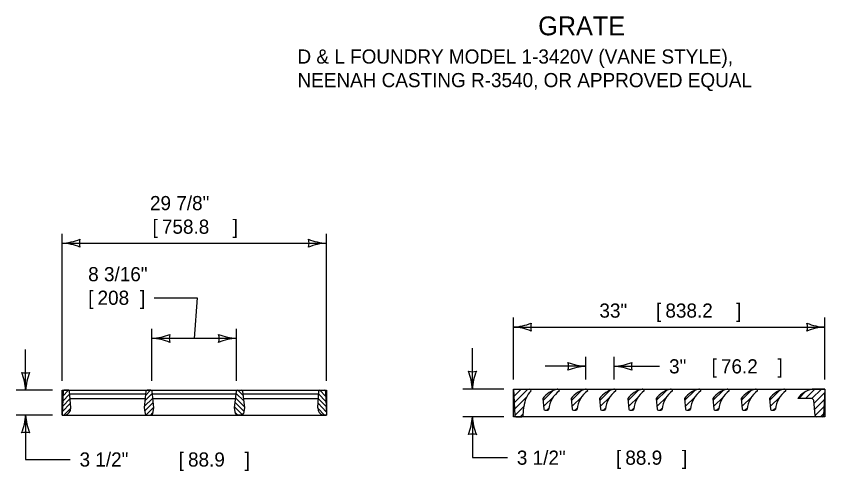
# Model space of a CAD drawing. Extents: x 49991.4 to 50041.6, y 49987.6 to 50011.4.
# Drawn here: x 50032.971 to 50036.399, y 49993.608 to 49995.536 of the extents above; entities that cross this region are included whole.
import ezdxf

# ---------------------------------------------------------------- set-up
doc = ezdxf.new("R2010")
doc.units = 0
for name, color, linetype in [('Default', 7, 'Continuous'), ('Level 1', 7, 'Continuous'), ('Level 2', 7, 'Continuous'), ('Level 3', 7, 'Continuous')]:
    doc.layers.add(name, color=color, linetype=linetype)

# ---------------------------------------------------------------- blocks, each defined once
blk = doc.blocks.new('POINT_DISPLAY')
at = {"layer": 'Default'}
blk.add_line((0, 0), (0, 0), dxfattribs=at)

msp = doc.modelspace()

# ---------------------------------------------------------------- linework, layer by layer
at = {"layer": 'Level 1'}
for p, q in [((50033.1659, 49993.934), (50033.1695, 49993.934)), ((50033.17, 49993.9459), (50033.1674, 49993.8783)), ((50033.1683, 49993.9023), (50033.1988, 49993.934)), ((50033.1692, 49993.9244), (50033.1934, 49993.9496)), ((50033.1943, 49993.9496), (50033.1737, 49993.9496)), ((50033.2026, 49993.8746), (50033.198, 49993.946)), ((50033.1988, 49993.934), (50033.5196, 49993.934)), ((50033.5209, 49993.9463), (50033.5134, 49993.8746)), ((50033.5165, 49993.9043), (50033.5483, 49993.9361)), ((50033.519, 49993.928), (50033.5406, 49993.9496)), ((50033.5418, 49993.9496), (50033.5263, 49993.9496)), ((50033.5547, 49993.8746), (50033.5472, 49993.9463)), ((50033.5485, 49993.934), (50033.9036, 49993.934)), ((50033.8974, 49993.8746), (50033.9049, 49993.9463)), ((50033.9356, 49993.9043), (50033.9038, 49993.9361)), ((50033.9103, 49993.9496), (50033.9258, 49993.9496)), ((50033.9331, 49993.928), (50033.9115, 49993.9496)), ((50033.9312, 49993.9463), (50033.9386, 49993.8746)), ((50033.9325, 49993.934), (50034.2533, 49993.934)), ((50034.2495, 49993.8746), (50034.254, 49993.946)), ((50034.2837, 49993.9023), (50034.2533, 49993.934)), ((50034.2578, 49993.9496), (50034.2783, 49993.9496)), ((50034.2829, 49993.9244), (50034.2587, 49993.9496)), ((50034.2821, 49993.9459), (50034.2846, 49993.8783)), ((50034.2825, 49993.934), (50034.2862, 49993.934)), ((50035.0786, 49993.9549), (50035.0845, 49993.8421)), ((50035.0786, 49993.9549), (50035.1461, 49993.9549)), ((50035.0786, 49993.8374), (50035.0786, 49993.9549)), ((50035.0788, 49993.9499), (50035.0839, 49993.9549)), ((50035.0802, 49993.923), (50035.1122, 49993.9549)), ((50035.0816, 49993.8961), (50035.1404, 49993.9549)), ((50035.2045, 49993.9058), (50035.2477, 49993.949)), ((50035.3245, 49993.9059), (50035.367, 49993.9484)), ((50035.4445, 49993.9059), (50035.487, 49993.9484)), ((50035.5645, 49993.9059), (50035.6071, 49993.9484)), ((50035.6845, 49993.9059), (50035.7271, 49993.9484)), ((50035.8045, 49993.9059), (50035.8471, 49993.9484)), ((50035.9245, 49993.9059), (50035.9671, 49993.9484)), ((50036.0445, 49993.9059), (50036.0871, 49993.9484)), ((50036.1645, 49993.9059), (50036.2071, 49993.9484)), ((50036.2885, 49993.9149), (50036.3173, 49993.9438)), ((50036.3168, 49993.9149), (50036.3568, 49993.9549)), ((50036.3442, 49993.9141), (50036.385, 49993.9549)), ((50036.3986, 49993.9549), (50036.3443, 49993.9549)), ((50036.3525, 49993.8941), (50036.3978, 49993.9394)), ((50036.3986, 49993.9549), (50036.3927, 49993.8421)), ((50033.1659, 49993.9141), (50033.1688, 49993.9141)), ((50033.1675, 49993.8802), (50033.2001, 49993.9141)), ((50033.2001, 49993.9141), (50033.5176, 49993.9141)), ((50033.5141, 49993.8806), (50033.5503, 49993.9168)), ((50033.5158, 49993.8612), (50033.5523, 49993.8976)), ((50033.5506, 49993.9141), (50033.9015, 49993.9141)), ((50033.9363, 49993.8612), (50033.8998, 49993.8976)), ((50033.938, 49993.8806), (50033.9018, 49993.9168)), ((50033.9345, 49993.9141), (50034.252, 49993.9141)), ((50034.2846, 49993.8802), (50034.252, 49993.9141)), ((50034.2833, 49993.9141), (50034.2862, 49993.9141)), ((50035.083, 49993.8692), (50035.1351, 49993.9213)), ((50035.2036, 49993.9149), (50035.2081, 49993.8694)), ((50035.207, 49993.8801), (50035.2489, 49993.9219)), ((50035.3236, 49993.9149), (50035.3281, 49993.8694)), ((50035.327, 49993.8802), (50035.37, 49993.9232)), ((50035.4436, 49993.9149), (50035.4481, 49993.8694)), ((50035.4471, 49993.8802), (50035.49, 49993.9231)), ((50035.5636, 49993.9149), (50035.5681, 49993.8694)), ((50035.5671, 49993.8802), (50035.61, 49993.9231)), ((50035.6836, 49993.9149), (50035.6882, 49993.8694)), ((50035.6871, 49993.8802), (50035.73, 49993.9231)), ((50035.8036, 49993.9149), (50035.8082, 49993.8694)), ((50035.8071, 49993.8802), (50035.8489, 49993.922)), ((50035.9236, 49993.9149), (50035.9282, 49993.8694)), ((50035.9271, 49993.8802), (50035.9689, 49993.922)), ((50036.0436, 49993.9149), (50036.0482, 49993.8694)), ((50036.0471, 49993.8802), (50036.0889, 49993.922)), ((50036.1636, 49993.9149), (50036.1682, 49993.8694)), ((50036.1671, 49993.8802), (50036.2089, 49993.922)), ((50036.342, 49993.9149), (50036.2836, 49993.9149)), ((50036.3571, 49993.842), (50036.3515, 49993.9058)), ((50036.3548, 49993.8681), (50036.3963, 49993.9095)), ((50033.1674, 49993.8783), (50033.1657, 49993.8446)), ((50033.1664, 49993.8578), (50033.2013, 49993.8943)), ((50033.1741, 49993.8446), (50033.2026, 49993.8744)), ((50033.5134, 49993.8746), (50033.5176, 49993.8508)), ((50033.5217, 49993.8458), (50033.5543, 49993.8784)), ((50033.5505, 49993.8508), (50033.5547, 49993.8746)), ((50033.9016, 49993.8508), (50033.8974, 49993.8746)), ((50033.9304, 49993.8458), (50033.8978, 49993.8784)), ((50033.9386, 49993.8746), (50033.9345, 49993.8508)), ((50034.278, 49993.8446), (50034.2495, 49993.8744)), ((50034.2857, 49993.8578), (50034.2507, 49993.8943)), ((50034.2846, 49993.8783), (50034.2863, 49993.8446)), ((50035.0845, 49993.8424), (50035.1235, 49993.8814)), ((50035.1199, 49993.842), (50035.1233, 49993.88)), ((50035.2131, 49993.8649), (50035.224, 49993.8649)), ((50035.2202, 49993.8649), (50035.2299, 49993.8746)), ((50035.3331, 49993.8649), (50035.344, 49993.8649)), ((50035.3401, 49993.8649), (50035.3501, 49993.8749)), ((50035.4531, 49993.8649), (50035.464, 49993.8649)), ((50035.4601, 49993.8649), (50035.4701, 49993.8749)), ((50035.5731, 49993.8649), (50035.584, 49993.8649)), ((50035.5801, 49993.8649), (50035.5901, 49993.8749)), ((50035.6931, 49993.8649), (50035.704, 49993.8649)), ((50035.7001, 49993.8649), (50035.7101, 49993.8749)), ((50035.8131, 49993.8649), (50035.824, 49993.8649)), ((50035.8201, 49993.8649), (50035.8304, 49993.8752)), ((50035.9331, 49993.8649), (50035.944, 49993.8649)), ((50035.9401, 49993.8649), (50035.9504, 49993.8752)), ((50036.0532, 49993.8649), (50036.0641, 49993.8649)), ((50036.0601, 49993.8649), (50036.0704, 49993.8752)), ((50036.1732, 49993.8649), (50036.1841, 49993.8649)), ((50036.1801, 49993.8649), (50036.1904, 49993.8752)), ((50036.3571, 49993.8421), (50036.3947, 49993.8797)), ((50033.1657, 49993.8446), (50033.1801, 49993.8446)), ((50033.1659, 49993.8446), (50034.2862, 49993.8446)), ((50033.525, 49993.8446), (50033.5431, 49993.8446)), ((50033.5417, 49993.8446), (50033.5511, 49993.854)), ((50033.9104, 49993.8446), (50033.901, 49993.854)), ((50033.9271, 49993.8446), (50033.909, 49993.8446)), ((50034.2863, 49993.8446), (50034.2719, 49993.8446)), ((50036.3986, 49993.8374), (50035.0786, 49993.8374)), ((50035.0895, 49993.8374), (50035.115, 49993.8374)), ((50035.1078, 49993.8374), (50035.1207, 49993.8503)), ((50036.3877, 49993.8374), (50036.3621, 49993.8374)), ((50036.3807, 49993.8374), (50036.3931, 49993.8498))]:
    msp.add_line(p, q, dxfattribs=at)
for points in [[(50033.1659, 49993.8446), (50033.1659, 49993.9496), (50034.2862, 49993.9496), (50034.2862, 49993.8446)], [(50035.0786, 49993.9549), (50036.3986, 49993.9549), (50036.3986, 49993.8374)]]:
    msp.add_lwpolyline(points, dxfattribs=at)
for centre, radius, start, end in [((50035.2354, 49993.8702), 0.1125, 136.6349, 175), ((50035.1461, 49993.9474), 0.0075, 0, 90), ((50035.2923, 49993.8457), 0.1125, 104.4608, 142.0572), ((50035.3408, 49993.8572), 0.1125, 126.7022, 173.7965), ((50035.2661, 49993.9474), 0.0075, 0, 104.4606), ((50035.4123, 49993.8457), 0.1125, 104.4608, 142.0572), ((50035.4608, 49993.8572), 0.1125, 126.7022, 173.7965), ((50035.3861, 49993.9474), 0.0075, 0, 104.4606), ((50035.5323, 49993.8457), 0.1125, 104.4608, 142.0572), ((50035.5808, 49993.8572), 0.1125, 126.7022, 173.7965), ((50035.5061, 49993.9474), 0.0075, 0, 104.4606), ((50035.6523, 49993.8457), 0.1125, 104.4607, 142.0571), ((50035.7008, 49993.8572), 0.1125, 126.7022, 173.7965), ((50035.6261, 49993.9474), 0.0075, 0, 104.4606), ((50035.7723, 49993.8457), 0.1125, 104.4607, 142.0571), ((50035.8208, 49993.8572), 0.1125, 126.7022, 173.7965), ((50035.7461, 49993.9474), 0.0075, 0, 104.4606), ((50035.8923, 49993.8457), 0.1125, 104.4607, 142.0571), ((50035.9409, 49993.8572), 0.1125, 126.7022, 173.7965), ((50035.8661, 49993.9474), 0.0075, 0, 104.4606), ((50036.0123, 49993.8457), 0.1125, 104.4607, 142.0571), ((50036.0609, 49993.8572), 0.1125, 126.7022, 173.7965), ((50035.9861, 49993.9474), 0.0075, 0, 104.4606), ((50036.1324, 49993.8457), 0.1125, 104.4607, 142.0571), ((50036.1809, 49993.8572), 0.1125, 126.7022, 173.7965), ((50036.1061, 49993.9474), 0.0075, 0, 104.4606), ((50036.2524, 49993.8457), 0.1125, 104.4607, 142.0571), ((50036.3009, 49993.8572), 0.1125, 126.7022, 173.7965), ((50036.2261, 49993.9474), 0.0075, 0, 104.4606), ((50036.3724, 49993.8457), 0.1125, 104.4606, 142.0571), ((50036.3462, 49993.9474), 0.0075, 90, 104.4606), ((50036.3415, 49993.9049), 0.01, 4.9999, 90), ((50035.2131, 49993.8699), 0.005, 185.7104, 270), ((50035.224, 49993.8699), 0.005, 270, 353.7963), ((50035.3331, 49993.8699), 0.005, 185.7104, 270), ((50035.344, 49993.8699), 0.005, 270, 353.7963), ((50035.4531, 49993.8699), 0.005, 185.7104, 270), ((50035.464, 49993.8699), 0.005, 270, 353.7963), ((50035.5731, 49993.8699), 0.005, 185.7104, 270), ((50035.584, 49993.8699), 0.005, 270, 353.7965), ((50035.6931, 49993.8699), 0.005, 185.7106, 270), ((50035.704, 49993.8699), 0.005, 270, 353.7965), ((50035.8131, 49993.8699), 0.005, 185.7106, 270), ((50035.824, 49993.8699), 0.005, 270, 353.7965), ((50035.9331, 49993.8699), 0.005, 185.7106, 270), ((50035.944, 49993.8699), 0.005, 270, 353.7965), ((50036.0532, 49993.8699), 0.005, 185.7106, 270), ((50036.0641, 49993.8699), 0.005, 270, 353.7965), ((50036.1732, 49993.8699), 0.005, 185.7106, 270), ((50036.1841, 49993.8699), 0.005, 270, 353.7965), ((50035.0895, 49993.8424), 0.005, 183, 270), ((50035.115, 49993.8424), 0.005, 270.0013, 355.0014), ((50035.1578, 49993.8274), 0.01, 81.6316, 90), ((50036.3194, 49993.8274), 0.01, 90, 98.3693), ((50036.3621, 49993.8424), 0.005, 185.0002, 270), ((50036.3877, 49993.8424), 0.005, 270, 356.9999)]:
    msp.add_arc(centre, radius, start, end, dxfattribs=at)
for centre, major_axis, ratio, start_param, end_param in [((50033.1737, 49993.9457), (0, 0.0039), 0.958653, 0, 1.518438), ((50033.1943, 49993.9457), (0, 0.0039), 0.958653, 4.799667, 6.283204), ((50033.5255, 49993.9449), (0.00476, 0), 0.99979, 1.388426, 2.855422), ((50033.5427, 49993.9449), (-0.00476, 0), 0.99979, 3.427776, 4.894775), ((50033.9094, 49993.9449), (0.00476, 0), 0.99979, 1.38841, 2.855409), ((50033.9266, 49993.9449), (-0.00476, 0), 0.99979, 3.427763, 4.894759), ((50034.2578, 49993.9457), (0, 0.0039), 0.958653, 6.283167, 7.766704), ((50034.2783, 49993.9457), (0, 0.0039), 0.958653, 4.764748, 6.283185), ((50033.1738, 49993.8739), (0, 0.03), 0.958653, 3.361832, 4.736544), ((50034.2782, 49993.8739), (0, 0.03), 0.958653, 1.546641, 2.921353), ((50033.525, 49993.8521), (-0.0075, 0), 0.99979, 0.174538, 1.570796), ((50033.5431, 49993.8521), (-0.0075, 0), 0.99979, 1.570796, 2.967065), ((50033.909, 49993.8521), (-0.0075, 0), 0.99979, 0.174528, 1.570796), ((50033.9271, 49993.8521), (-0.0075, 0), 0.99979, 1.570796, 2.967054)]:
    msp.add_ellipse(centre, major_axis=major_axis, ratio=ratio, start_param=start_param, end_param=end_param, dxfattribs=at)
at = {"layer": 'Level 3'}
for p, q in [((50033.1659, 49993.9896), (50033.1659, 49994.6135)), ((50034.2862, 49993.9896), (50034.2862, 49994.6135)), ((50033.1659, 49994.5735), (50034.2862, 49994.5735)), ((50035.0786, 49993.9949), (50035.0786, 49994.2576)), ((50036.3986, 49993.9949), (50036.3986, 49994.2576)), ((50033.5469, 49993.9896), (50033.5469, 49994.2097)), ((50033.9052, 49993.9896), (50033.9052, 49994.2097)), ((50035.0786, 49994.2176), (50036.3986, 49994.2176)), ((50033.9052, 49994.1697), (50033.5469, 49994.1697)), ((50033.0116, 49993.9496), (50033.0116, 49994.123)), ((50034.9049, 49993.9549), (50034.9049, 49994.1283)), ((50035.3861, 49993.9949), (50035.3861, 49994.0912)), ((50035.5052, 49993.9949), (50035.5052, 49994.0912)), ((50035.3861, 49994.0512), (50035.2127, 49994.0512)), ((50035.5052, 49994.0512), (50035.6985, 49994.0512)), ((50033.1259, 49993.9496), (50032.9716, 49993.9496)), ((50035.0386, 49993.9549), (50034.8649, 49993.9549)), ((50033.1257, 49993.8446), (50032.9714, 49993.8446)), ((50035.0386, 49993.8374), (50034.8649, 49993.8374)), ((50034.9049, 49993.8374), (50034.9049, 49993.6638)), ((50034.9049, 49993.6638), (50035.0534, 49993.6638))]:
    msp.add_line(p, q, dxfattribs=at)
for points in [[(50033.5561, 49994.3421), (50033.7379, 49994.3421), (50033.726, 49994.1697)], [(50033.0114, 49993.8446), (50033.0114, 49993.656), (50033.2, 49993.656)]]:
    msp.add_lwpolyline(points, dxfattribs=at)
for centre, radius, start, end in [((50033.1544, 49994.8062), 0.233, 272.8273, 292.0772), ((50033.1544, 49994.8062), 0.233, 272.8273, 292.0772), ((50033.2941, 49994.5735), 0.0548, 162.1388, 197.8612), ((50033.2941, 49994.5735), 0.0548, 162.1388, 197.8612), ((50034.2953, 49994.7956), 0.2223, 247.456, 267.6395), ((50034.158, 49994.5735), 0.0548, 342.1388, 17.8612), ((50034.2953, 49994.7956), 0.2223, 247.456, 267.6395), ((50034.158, 49994.5735), 0.0548, 342.1388, 17.8612), ((50033.1567, 49994.3513), 0.2223, 67.456, 87.6395), ((50033.1567, 49994.3513), 0.2223, 67.456, 87.6395), ((50034.2977, 49994.3407), 0.233, 92.8273, 112.0772), ((50034.2977, 49994.3407), 0.233, 92.8273, 112.0772), ((50035.0671, 49994.4503), 0.233, 272.8273, 292.0772), ((50035.0671, 49994.4503), 0.233, 272.8273, 292.0772), ((50035.0694, 49993.9955), 0.2223, 67.456, 87.6395), ((50035.0694, 49993.9955), 0.2223, 67.456, 87.6395), ((50035.2068, 49994.2176), 0.0548, 162.1388, 197.8612), ((50035.2068, 49994.2176), 0.0548, 162.1388, 197.8612), ((50036.4078, 49994.4397), 0.2223, 247.456, 267.6395), ((50036.2704, 49994.2176), 0.0548, 342.1388, 17.8612), ((50036.4101, 49993.9849), 0.233, 92.8273, 112.0772), ((50033.5354, 49994.4024), 0.233, 272.8273, 292.0772), ((50033.5354, 49994.4024), 0.233, 272.8273, 292.0772), ((50033.6751, 49994.1697), 0.0548, 162.1388, 197.8612), ((50033.6751, 49994.1697), 0.0548, 162.1388, 197.8612), ((50033.9144, 49994.3919), 0.2223, 247.456, 267.6395), ((50033.777, 49994.1697), 0.0548, 342.1388, 17.8612), ((50033.5377, 49993.9476), 0.2223, 67.456, 87.6395), ((50033.5377, 49993.9476), 0.2223, 67.456, 87.6395), ((50033.9167, 49993.937), 0.233, 92.8273, 112.0772), ((50035.3953, 49994.2733), 0.2223, 247.456, 267.6395), ((50035.2579, 49994.0512), 0.0548, 342.1388, 17.8612), ((50035.3953, 49994.2733), 0.2223, 247.456, 267.6395), ((50035.2579, 49994.0512), 0.0548, 342.1388, 17.8612), ((50035.4937, 49994.2839), 0.233, 272.8273, 292.0772), ((50035.4937, 49994.2839), 0.233, 272.8273, 292.0772), ((50035.6334, 49994.0512), 0.0548, 162.1388, 197.8612), ((50035.6334, 49994.0512), 0.0548, 162.1388, 197.8612), ((50035.3976, 49993.8185), 0.233, 92.8273, 112.0772), ((50035.3976, 49993.8185), 0.233, 92.8273, 112.0772), ((50035.496, 49993.8291), 0.2223, 67.456, 87.6395), ((50035.496, 49993.8291), 0.2223, 67.456, 87.6395), ((50033.0116, 49994.0778), 0.0548, 252.1388, 287.8612), ((50032.7789, 49993.9381), 0.233, 2.8273, 22.0772), ((50033.0116, 49994.0778), 0.0548, 252.1388, 287.8612), ((50032.7789, 49993.9381), 0.233, 2.8273, 22.0772), ((50033.2337, 49993.9404), 0.2223, 157.456, 177.6395), ((50033.2337, 49993.9404), 0.2223, 157.456, 177.6395), ((50034.9049, 49994.0831), 0.0548, 252.1388, 287.8612), ((50034.6722, 49993.9434), 0.233, 2.8273, 22.0772), ((50034.9049, 49994.0831), 0.0548, 252.1388, 287.8612), ((50034.6722, 49993.9434), 0.233, 2.8273, 22.0772), ((50035.127, 49993.9458), 0.2223, 157.456, 177.6395), ((50035.127, 49993.9458), 0.2223, 157.456, 177.6395), ((50032.7893, 49993.8538), 0.2223, 337.456, 357.6395), ((50033.2441, 49993.8561), 0.233, 182.8273, 202.0772), ((50034.6828, 49993.8466), 0.2223, 337.456, 357.6395), ((50035.1376, 49993.8489), 0.233, 182.8273, 202.0772), ((50033.0114, 49993.7164), 0.0548, 72.1388, 107.8612), ((50034.9049, 49993.7092), 0.0548, 72.1388, 107.8612)]:
    msp.add_arc(centre, radius, start, end, dxfattribs=at)

# ---------------------------------------------------------------- block references
at = {"layer": 'Level 1', "xscale": 1.574803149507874, "yscale": 1.574803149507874}
for p in [(50035.1536, 49993.9482), (50035.2736, 49993.9482)]:
    msp.add_blockref('POINT_DISPLAY', p, dxfattribs=at)

# ---------------------------------------------------------------- texts
at = {"layer": 'Level 2'}
for s, height, p in [('GRATE', 0.08, (50035.1838, 49995.4552)), ('D & L FOUNDRY MODEL 1-3420V (VANE STYLE),', 0.06, (50034.1636, 49995.3352)), ('NEENAH CASTING R-3540, OR APPROVED EQUAL', 0.06, (50034.1636, 49995.2352)), ('29 7/8"', 0.06, (50033.5385, 49994.7135)), ('[', 0.06, (50033.5493, 49994.6135)), ('758.8', 0.06, (50033.589, 49994.6135)), (']', 0.06, (50033.889, 49994.6135)), ('8 3/16"', 0.06, (50033.2766, 49994.4121)), ('[', 0.06, (50033.2766, 49994.3121)), ('208', 0.06, (50033.3163, 49994.3121)), (']', 0.06, (50033.4963, 49994.3121)), ('33" ', 0.06, (50035.4432, 49994.2576)), ('[', 0.06, (50035.6832, 49994.2576)), ('838.2', 0.06, (50035.7229, 49994.2576)), (']', 0.06, (50036.0229, 49994.2576)), ('3" ', 0.06, (50035.7385, 49994.0212)), ('[', 0.06, (50035.9185, 49994.0212)), ('76.2', 0.06, (50035.9582, 49994.0212)), (']', 0.06, (50036.1982, 49994.0212)), ('3 1/2" ', 0.06, (50035.0934, 49993.6338)), ('[', 0.06, (50035.5134, 49993.6338)), ('88.9', 0.06, (50035.5531, 49993.6338)), (']', 0.06, (50035.7931, 49993.6338)), ('3 1/2" ', 0.06, (50033.24, 49993.626)), ('[', 0.06, (50033.66, 49993.626)), ('88.9', 0.06, (50033.6997, 49993.626)), (']', 0.06, (50033.9397, 49993.626))]:
    msp.add_text(s, height=height, dxfattribs=at).set_placement(p)

doc.saveas('drawing.dxf')
